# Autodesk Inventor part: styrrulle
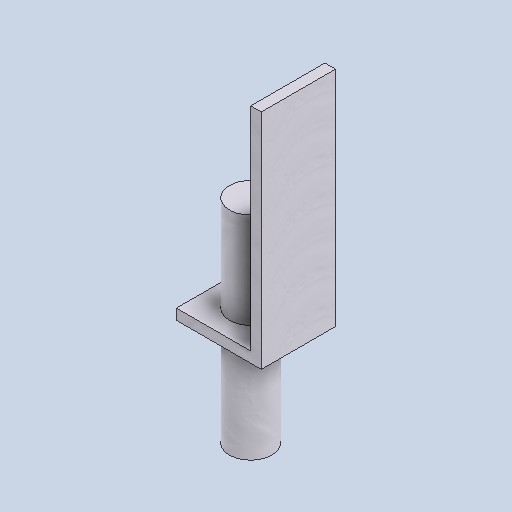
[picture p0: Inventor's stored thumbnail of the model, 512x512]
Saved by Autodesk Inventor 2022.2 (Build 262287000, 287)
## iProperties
Created: 2019-06
Part Number: styrrulle
Material: Aluminum 6061, Welded
Document SubType Name: Modeling
Designer: cl
Density: 2.7 g/cm^3
Appearance: Weld - Aluminum
Author: cl
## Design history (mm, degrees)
sketch "Sketch1"
  geometry: L1 (0, 0)-(40, 0); L2 (40, 0)-(40, -35); L3 (40, -35)-(0, -35); L4 (0, -35)-(0, 0)
  constraints: 8 end point, 2 parallel, 1 horizontal, 1 perpendicular
  dimensions: "d0" = 40 distance of L2.end L3.end; "d1" = 35 distance of L1.end L2.end
extrude "Extrusion1" new body sketch "Sketch1" distance "d2" = 5; taper "d3" = 0 deg
sketch "Sketch2"
  geometry: L1 (0, 0)-(0, 35) reference; L2 (0, 35)-(-40, 35) reference; L3 (0, 0)-(-5, 0); L4 (-5, 0)-(-5, 35); L5 (-5, 35)-(0, 35); L6 (0, 35)-(0, 0); 1 further point
  constraints: 8 end point, 2 parallel, 1 horizontal, 1 perpendicular, 1 point on line
  dimensions: "d4" = 5 distance of L4.end L5.end
extrude "Extrusion2" join sketch "Sketch2" distance "d5" = 100; taper "d6" = 0 deg
sketch "Sketch3"
  geometry: L1 (-40, -35)-(-40, 0) reference; L2 (-40, 0)-(0, 0) reference; C1 r 10 at (-22.5, -17.5)
  constraints: 1 centre point
  dimensions: "d7" = 17.5 distance from line of L1 C1.centre; "d8" = 17.5 distance from line of L2 C1.centre; "d9" = 20 diameter of C1
extrude "Extrusion3" join sketch "Sketch3" distance "d10" = 50; taper "d12" = 0 deg; dims "d11" = 50, "d13" = 0
body "Solid1"
